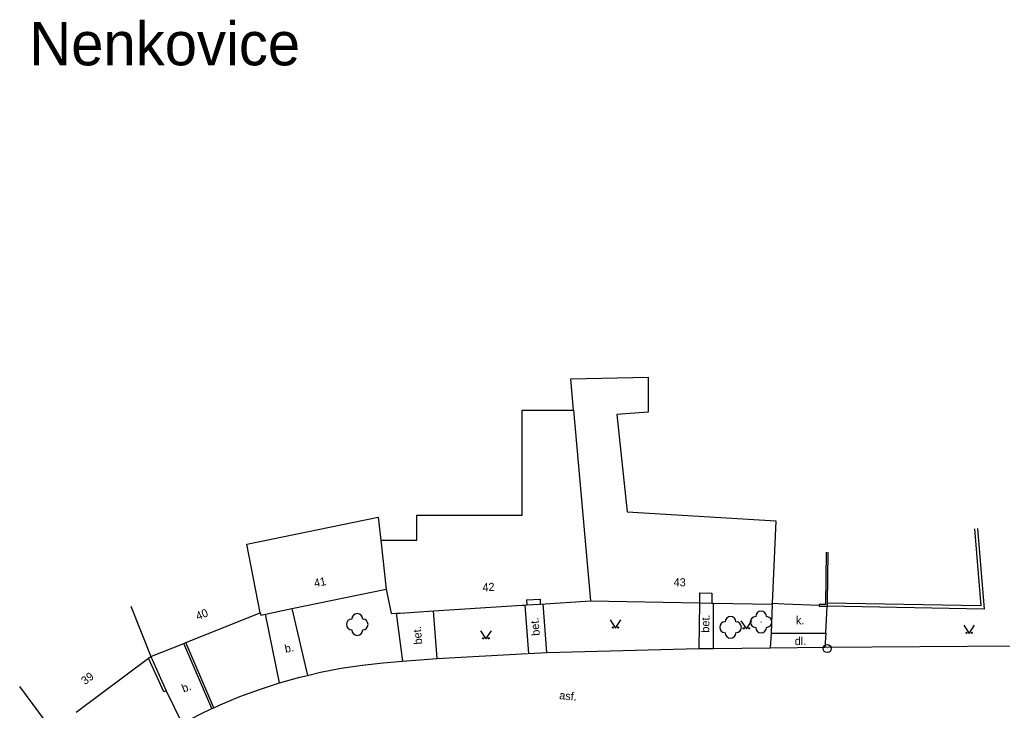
# Model space of a CAD drawing. Extents: x -582162 to -561283, y -1187583 to -1183539.
# Drawn here: x -571092.7 to -571002.1, y -1184925.8 to -1184862.1 of the extents above; entities that cross this region are included whole.
import ezdxf

# ---------------------------------------------------------------- set-up
doc = ezdxf.new("R2010")
doc.units = 0
for name, color, linetype in [('Vrstva 1', 7, 'Continuous'), ('Vrstva 10', 7, 'Continuous'), ('Vrstva 11', 7, 'Continuous'), ('Vrstva 14', 7, 'Continuous'), ('Vrstva 17', 7, 'Continuous'), ('Vrstva 3', 7, 'Continuous'), ('Vrstva 4', 7, 'Continuous'), ('Vrstva 5', 7, 'Continuous'), ('Vrstva 6', 7, 'Continuous'), ('Vrstva 9', 7, 'Continuous')]:
    doc.layers.add(name, color=color, linetype=linetype)

# ---------------------------------------------------------------- blocks, each defined once
blk = doc.blocks.new('1.079')
at = {"layer": 'Vrstva 1'}
for radius in [0.75, 0.001]:
    blk.add_circle((0, -0.001), radius, dxfattribs=at)
blk = doc.blocks.new('3.130')
at = {"layer": 'Vrstva 1'}
blk.add_circle((0, 0), 0.001, dxfattribs=at)
for centre, start, end in [((0, 1), 0, 180), ((-1, 0), 90, 270), ((1, 0), 270, 90), ((0, -1), 180, 360)]:
    blk.add_arc(centre, 1, start, end, dxfattribs=at)
blk = doc.blocks.new('3.140')
at = {"layer": 'Vrstva 1'}
blk.add_lwpolyline([(-1, 1.5), (0, 0), (1, 1.5)], dxfattribs=at)
for centre in [(-0.5, 0.1), (0.5, 0.1)]:
    blk.add_circle(centre, 0.1, dxfattribs=at)

msp = doc.modelspace()

# ---------------------------------------------------------------- linework, layer by layer
at = {"layer": 'Vrstva 10'}
for points in [[(-571030.04, -1184915.9), (-571030.1, -1184920.1)], [(-571028.74, -1184920.09), (-571028.73, -1184915.92)], [(-571067.61, -1184916.43), (-571066.19, -1184922.59)], [(-571054.23, -1184921.02), (-571054.55, -1184916.64)], [(-571046.14, -1184916.1), (-571045.81, -1184920.55)], [(-571044.12, -1184920.47), (-571044.46, -1184915.99)], [(-571023.34, -1184916.02), (-571023.41, -1184918.7)], [(-571018.37, -1184918.69), (-571018.27, -1184916.21)], [(-571068.77, -1184923.28), (-571070.05, -1184916.93)], [(-571058.01, -1184916.86), (-571057.41, -1184921.28)], [(-571023.41, -1184918.7), (-571023.5, -1184920.03)], [(-571023.41, -1184918.7), (-571018.37, -1184918.69)], [(-571018.37, -1184918.69), (-571018.47, -1184919.98)], [(-571045.81, -1184920.55), (-571044.12, -1184920.47)], [(-571044.12, -1184920.47), (-571030.1, -1184920.1)], [(-571030.1, -1184920.1), (-571028.74, -1184920.09)], [(-571028.74, -1184920.09), (-571023.5, -1184920.03)], [(-571023.5, -1184920.03), (-571018.47, -1184919.98)], [(-571018.47, -1184919.98), (-571000.94, -1184919.85)], [(-571066.19, -1184922.59), (-571064.97, -1184922.3), (-571063.06, -1184921.93), (-571061.13, -1184921.65), (-571059.19, -1184921.44), (-571057.41, -1184921.28)], [(-571057.41, -1184921.28), (-571054.23, -1184921.02)], [(-571054.23, -1184921.02), (-571045.9, -1184920.56)], [(-571068.77, -1184923.28), (-571066.87, -1184922.75), (-571066.19, -1184922.59)], [(-571079.21, -1184924.01), (-571077.73, -1184927.01)], [(-571074.8, -1184925.56), (-571074.23, -1184925.29), (-571072.43, -1184924.54), (-571070.6, -1184923.87), (-571068.77, -1184923.28)], [(-571077.73, -1184927.01), (-571076, -1184926.12), (-571074.99, -1184925.65)], [(-571074.99, -1184925.65), (-571074.8, -1184925.56)]]:
    msp.add_lwpolyline(points, dxfattribs=at)
at = {"layer": 'Vrstva 4'}
for points in [[(-571067.61, -1184916.43), (-571058.92, -1184914.64)], [(-571058.92, -1184914.64), (-571058.47, -1184916.89), (-571058.01, -1184916.86), (-571057.64, -1184916.84)], [(-571030.02, -1184914.97), (-571030.04, -1184915.9)], [(-571028.89, -1184914.99), (-571028.9, -1184915.92)], [(-571045.98, -1184915.63), (-571045.96, -1184916.09)], [(-571044.73, -1184915.54), (-571044.72, -1184916.01)], [(-571044.72, -1184916.01), (-571040.08, -1184915.72)], [(-571040.08, -1184915.72), (-571030.04, -1184915.9)], [(-571030.04, -1184915.9), (-571028.9, -1184915.92)], [(-571028.9, -1184915.92), (-571028.73, -1184915.92), (-571023.34, -1184916.02)], [(-571023.34, -1184916.02), (-571023.34, -1184915.92)], [(-571082.47, -1184916.21), (-571080.62, -1184920.85)], [(-571077.39, -1184919.56), (-571070.53, -1184916.82)], [(-571070.53, -1184916.82), (-571070.49, -1184917.02), (-571070.05, -1184916.93)], [(-571070.05, -1184916.93), (-571067.61, -1184916.43)], [(-571057.64, -1184916.84), (-571054.55, -1184916.64)], [(-571054.55, -1184916.64), (-571046.37, -1184916.12)], [(-571046.37, -1184916.12), (-571046.22, -1184916.11)], [(-571046.22, -1184916.11), (-571045.96, -1184916.09)], [(-571045.96, -1184916.09), (-571044.72, -1184916.01)], [(-571077.57, -1184919.63), (-571077.39, -1184919.56)], [(-571080.62, -1184920.85), (-571077.57, -1184919.63)], [(-571087.51, -1184925.96), (-571080.83, -1184921)], [(-571080.83, -1184921), (-571080.62, -1184920.85)], [(-571092.72, -1184923.6), (-571089.74, -1184927.62)]]:
    msp.add_lwpolyline(points, dxfattribs=at)
at = {"layer": 'Vrstva 5'}
for points in [[(-571041.65, -1184898.12), (-571041.88, -1184895.24), (-571034.77, -1184895.1), (-571034.77, -1184898.32), (-571037.65, -1184898.52), (-571036.71, -1184907.51), (-571022.99, -1184908.33), (-571023.34, -1184915.92)], [(-571059.42, -1184910.13), (-571056.08, -1184910.13), (-571056.08, -1184907.81), (-571046.39, -1184907.81), (-571046.39, -1184898.12), (-571041.65, -1184898.12), (-571040.08, -1184915.72)], [(-571070.53, -1184916.82), (-571071.76, -1184910.48), (-571059.66, -1184908), (-571059.42, -1184910.13), (-571058.92, -1184914.64)]]:
    msp.add_lwpolyline(points, dxfattribs=at)
at = {"layer": 'Vrstva 9'}
for points in [[(-571004.38, -1184909.05), (-571003.77, -1184916.47), (-571018.27, -1184916.21)], [(-571004.68, -1184909.07), (-571004.1, -1184916.16), (-571018.27, -1184915.91)], [(-571018.34, -1184911.21), (-571018.41, -1184916.06), (-571019.01, -1184916.05), (-571019.01, -1184916.12)], [(-571018.19, -1184911.21), (-571018.27, -1184915.91)], [(-571030.02, -1184914.97), (-571028.89, -1184914.99)], [(-571045.98, -1184915.63), (-571044.73, -1184915.54)], [(-571023.34, -1184915.92), (-571022.22, -1184915.98), (-571019.01, -1184916.12)], [(-571018.27, -1184915.91), (-571018.27, -1184916.21)], [(-571019.01, -1184916.12), (-571019.01, -1184916.2), (-571018.27, -1184916.21)], [(-571074.8, -1184925.56), (-571077.39, -1184919.56)], [(-571074.99, -1184925.65), (-571077.57, -1184919.63)], [(-571079.21, -1184924.01), (-571079.44, -1184924.11), (-571080.83, -1184921)], [(-571080.62, -1184920.85), (-571079.21, -1184924.01)]]:
    msp.add_lwpolyline(points, dxfattribs=at)

# ---------------------------------------------------------------- block references
at = {"layer": 'Vrstva 1', "xscale": 0.5, "yscale": 0.5}
msp.add_blockref('1.079', (-571018.26, -1184920.11), dxfattribs=at)
at = {"layer": 'Vrstva 11', "xscale": 0.5, "yscale": 0.5}
for p in [(-571024.35, -1184917.66), (-571061.59, -1184917.89), (-571027.17, -1184918.15)]:
    msp.add_blockref('3.130', p, dxfattribs=at)
at = {"layer": 'Vrstva 3', "xscale": 0.5, "yscale": 0.5}
for p in [(-571037.77, -1184918.22), (-571025.71, -1184918.29), (-571049.72, -1184919.22), (-571005.16, -1184918.71)]:
    msp.add_blockref('3.140', p, dxfattribs=at)

# ---------------------------------------------------------------- texts
at = {"layer": 'Vrstva 14'}
for s, rotation, p in [('bet.', 94.928, (-571044.75, -1184918.9)), ('bet.', 88.588, (-571029.14, -1184918.65)), ('k.', 0.148, (-571021.14, -1184917.88)), ('bet.', 94.928, (-571055.59, -1184919.7)), ('dl.', 0.148, (-571021.25, -1184919.79)), ('b.', 11.603, (-571068.2, -1184920.51)), ('b.', 21.762, (-571077.6, -1184924.17)), ('asf.', 354.308, (-571042.99, -1184924.77))]:
    msp.add_text(s, height=0.75, rotation=rotation, dxfattribs=at).set_placement(p)
at = {"layer": 'Vrstva 17'}
msp.add_text('Nenkovice', height=4, dxfattribs=at).set_placement((-571091.83, -1184866.34))
at = {"layer": 'Vrstva 6'}
for s, rotation, p in [('41', 11.607, (-571065.5, -1184914.46)), ('42', 3.634, (-571050.02, -1184914.85)), ('43', 358.956, (-571032.42, -1184914.36)), ('40', 21.765, (-571076.3, -1184917.51)), ('39', 36.596, (-571086.7, -1184923.49))]:
    msp.add_text(s, height=0.75, rotation=rotation, dxfattribs=at).set_placement(p)

doc.saveas('drawing.dxf')
